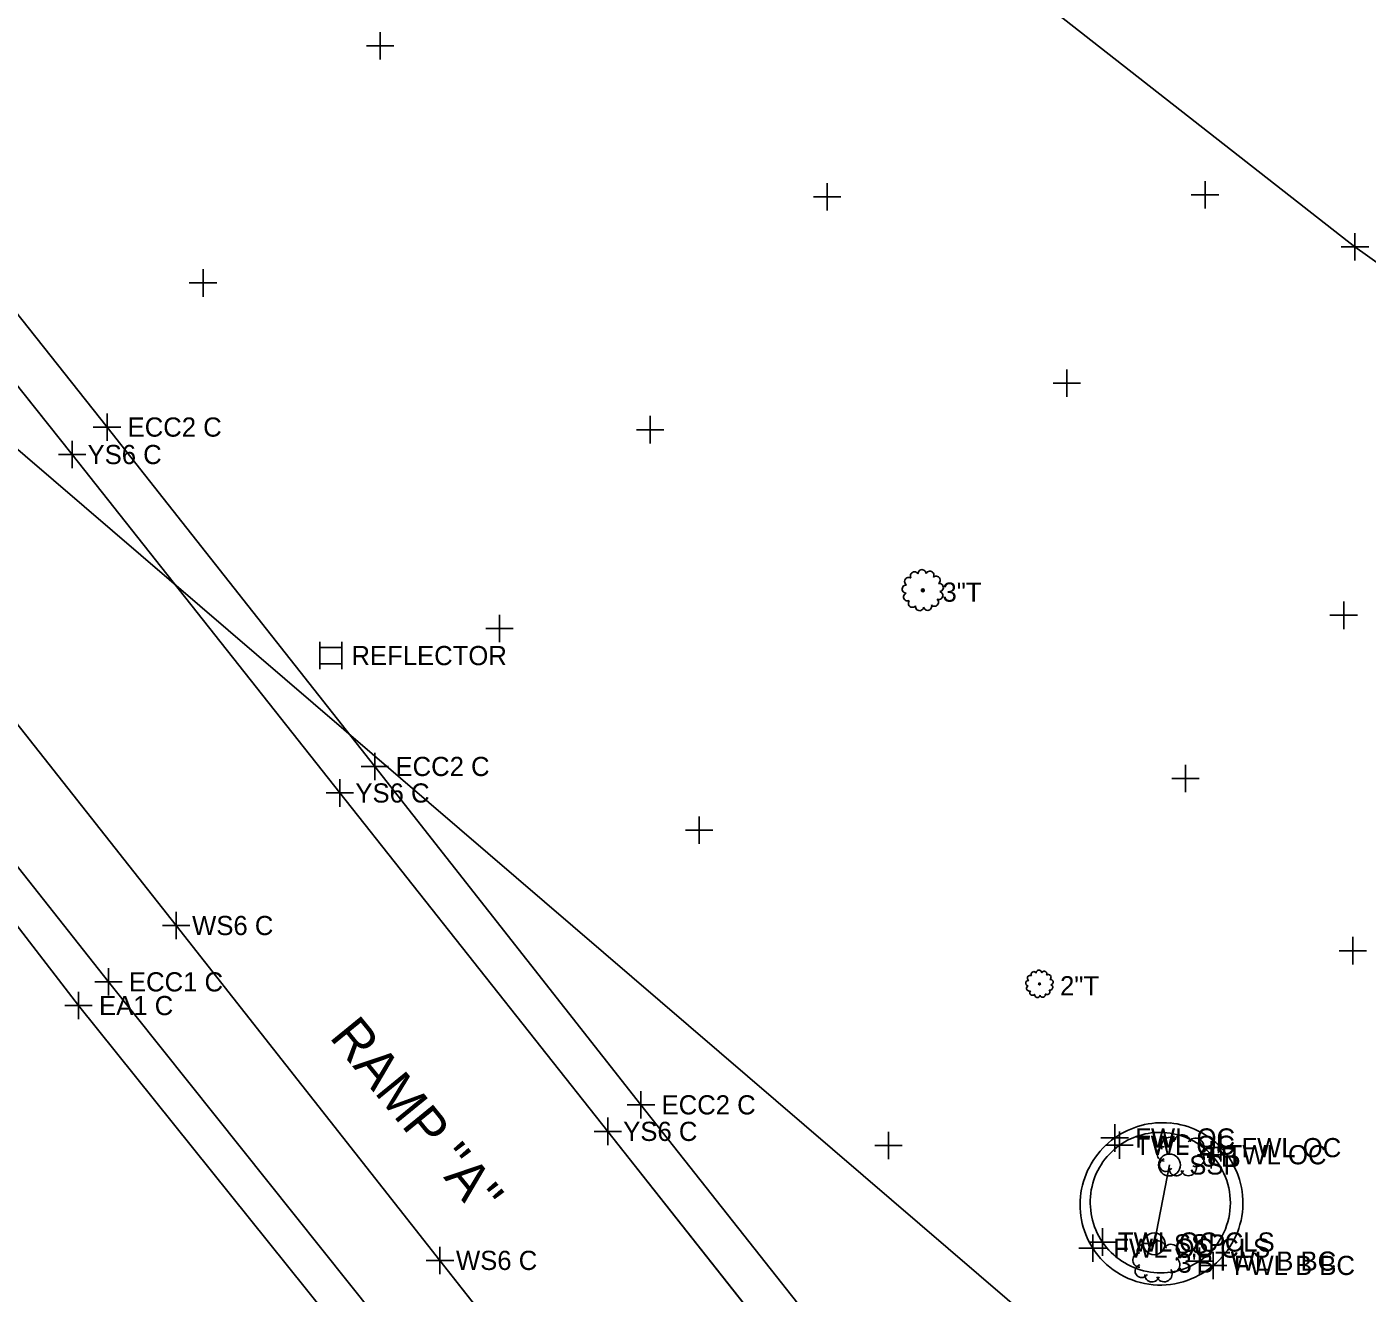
# Model space of a CAD drawing. Extents: x 1324236 to 1326110, y 459090 to 460782.
# Drawn here: x 1324868.3 to 1324966.1, y 460001.4 to 460093.8 of the extents above; entities that cross this region are included whole.
import ezdxf

# ---------------------------------------------------------------- set-up
doc = ezdxf.new("R2010")
doc.units = 0
for name, color, linetype in [('DR_X_Ditch', 7, 'Continuous'), ('DR_X_Drive_Pipe', 7, 'Continuous'), ('DT_X_Contour_Minor', 7, 'Continuous'), ('DT_X_Contour_Text', 7, 'Continuous'), ('DT_X_Terrain_Ground_Line', 7, 'Continuous'), ('DV_X_Property_Line', 7, 'Continuous'), ('E-RW-ODOT', 7, 'Continuous'), ('PM_X_Edge_Line', 7, 'Continuous'), ('PV_X_Shoulder', 7, 'Continuous'), ('RD_X_Text', 7, 'Continuous'), ('RW_X_CL', 7, 'Continuous'), ('RW_X_Esmt_SH', 7, 'Continuous'), ('VG_X_Cells', 7, 'Continuous')]:
    doc.layers.add(name, color=color, linetype=linetype)

msp = doc.modelspace()

# ---------------------------------------------------------------- linework, layer by layer
at = {"layer": 'DR_X_Ditch'}
for points in [[(1324931.111, 459987.395), (1324910.705, 460013.214), (1324891.166, 460037.899), (1324871.627, 460062.59), (1324850.878, 460088.64)], [(1324972.418, 459899.148), (1324970.516, 459905.873), (1324967.972, 459912.382), (1324967.972, 459912.382), (1324965.028, 459918.226), (1324961.566, 459923.779), (1324957.615, 459928.995), (1324957.615, 459928.995), (1324938.831, 459952.603), (1324918.889, 459977.836), (1324898.462, 460003.802), (1324879.212, 460028.231), (1324859.572, 460053.099)]]:
    msp.add_lwpolyline(points, dxfattribs=at)
at = {"layer": 'DR_X_Drive_Pipe'}
for p, q in [((1324939.235, 460098.091), (1324965.213, 460077.743)), ((1324965.213, 460077.743), (1324995.01, 460056.453))]:
    msp.add_line(p, q, dxfattribs=at)
at = {"layer": 'DT_X_Contour_Minor'}
msp.add_line((1324950.563, 460005.008), (1324951.678, 460010.762), dxfattribs=at)
for centre in [(1324951.678, 460010.762), (1324950.563, 460005.008)]:
    msp.add_circle(centre, 0.8, dxfattribs=at)
at = {"layer": 'DT_X_Contour_Text'}
for centre, radius, start, end in [((1324951.177, 460007.826), 6.022, 84.80157, 125.45455), ((1324950.975, 460008.06), 5.075, 84.09181, 125.30471), ((1324950.965, 460007.964), 5.17, 43.27985, 84.09181), ((1324951.193, 460008.002), 5.846, 43.51192, 84.80157), ((1324951.183, 460007.819), 6.032, 125.45455, 168.70241), ((1324950.975, 460008.06), 5.074, 125.30471, 169.93461), ((1324950.998, 460007.995), 5.125, 353.72059, 43.27985), ((1324951.189, 460007.998), 5.852, 356.25143, 43.51192), ((1324951.005, 460007.854), 5.85, 168.70241, 212.65042), ((1324951.07, 460008.043), 5.171, 169.93461, 214.12344), ((1324950.983, 460007.997), 5.14, 304.23642, 353.72059), ((1324951.152, 460008.001), 5.889, 309.14866, 356.25143), ((1324951.011, 460007.858), 5.858, 212.65042, 261.81789), ((1324951.031, 460008.017), 5.125, 214.12344, 258.87056), ((1324951.034, 460008.033), 5.141, 258.87056, 303.54359), ((1324951.016, 460007.896), 5.896, 261.81789, 310.81428)]:
    msp.add_arc(centre, radius, start, end, dxfattribs=at)
at = {"layer": 'DT_X_Terrain_Ground_Line'}
for p, q in [((1324889.704, 460048.924), (1324889.704, 460046.924)), ((1324889.704, 460048.524), (1324891.304, 460048.524)), ((1324891.304, 460048.924), (1324891.304, 460046.924)), ((1324889.704, 460047.323), (1324891.304, 460047.323))]:
    msp.add_line(p, q, dxfattribs=at)
at = {"layer": 'DV_X_Property_Line'}
for p, q in [((1324874.175, 460063.594), (1324874.175, 460065.594)), ((1324873.175, 460064.594), (1324875.175, 460064.594)), ((1324893.717, 460038.834), (1324893.717, 460040.834)), ((1324892.717, 460039.834), (1324894.717, 460039.834)), ((1324874.274, 460023.121), (1324874.274, 460025.121)), ((1324873.274, 460024.121), (1324875.274, 460024.121)), ((1324872.092, 460021.391), (1324872.092, 460023.391)), ((1324871.092, 460022.391), (1324873.092, 460022.391)), ((1324913.127, 460014.149), (1324913.127, 460016.149)), ((1324912.127, 460015.149), (1324914.127, 460015.149)), ((1324947.684, 460011.732), (1324947.684, 460013.732)), ((1324948.042, 460011.201), (1324948.042, 460013.201)), ((1324946.684, 460012.732), (1324948.684, 460012.732)), ((1324947.042, 460012.201), (1324949.042, 460012.201)), ((1324954.729, 460010.509), (1324954.729, 460012.509)), ((1324955.433, 460011.027), (1324955.433, 460013.027)), ((1324953.729, 460011.509), (1324955.729, 460011.509)), ((1324954.433, 460012.027), (1324956.433, 460012.027)), ((1324946.079, 460003.698), (1324946.079, 460005.698)), ((1324946.789, 460004.142), (1324946.789, 460006.142)), ((1324945.079, 460004.698), (1324947.079, 460004.698)), ((1324945.789, 460005.142), (1324947.789, 460005.142)), ((1324953.875, 460002.748), (1324953.875, 460004.748)), ((1324954.87, 460002.434), (1324954.87, 460004.434)), ((1324952.875, 460003.748), (1324954.875, 460003.748)), ((1324953.87, 460003.434), (1324955.87, 460003.434))]:
    msp.add_line(p, q, dxfattribs=at)
at = {"layer": 'E-RW-ODOT'}
msp.add_line((1324967.69, 459977.085), (1324507.192, 460372.321), dxfattribs=at)
at = {"layer": 'PM_X_Edge_Line'}
for p, q in [((1324871.627, 460062.59), (1324850.878, 460088.64)), ((1324891.166, 460037.899), (1324871.627, 460062.59)), ((1324879.212, 460028.231), (1324859.572, 460053.099)), ((1324910.705, 460013.214), (1324891.166, 460037.899)), ((1324898.462, 460003.802), (1324879.212, 460028.231)), ((1324931.111, 459987.395), (1324910.705, 460013.214)), ((1324918.889, 459977.836), (1324898.462, 460003.802))]:
    msp.add_line(p, q, dxfattribs=at)
at = {"layer": 'PV_X_Shoulder'}
for points in [[(1325002.148, 459921.478), (1324996.212, 459922.965), (1324990.513, 459925.196), (1324985.145, 459928.133), (1324985.145, 459928.133), (1324980.413, 459931.549), (1324976.131, 459935.514), (1324972.361, 459939.969), (1324972.361, 459939.969), (1324953.276, 459964.235), (1324933.65, 459989.173), (1324913.127, 460015.149), (1324893.717, 460039.834), (1324874.175, 460064.594), (1324853.444, 460090.73)], [(1324963.956, 459891.113), (1324963.664, 459897.313), (1324962.677, 459903.442), (1324961.01, 459909.421), (1324961.01, 459909.421), (1324958.808, 459914.907), (1324956.032, 459920.127), (1324952.714, 459925.02), (1324952.714, 459925.02), (1324933.824, 459948.865), (1324913.964, 459974.1), (1324893.683, 459999.816), (1324874.274, 460024.121), (1324854.57, 460049.078)], [(1324963.229, 459890.886), (1324962.765, 459896.504), (1324961.703, 459902.039), (1324960.055, 459907.43), (1324960.055, 459907.43), (1324957.85, 459912.595), (1324955.106, 459917.495), (1324951.857, 459922.075), (1324951.857, 459922.075), (1324931.855, 459947.295), (1324912.156, 459972.555), (1324891.509, 459998.228), (1324872.092, 460022.391), (1324852.737, 460047.518)]]:
    msp.add_lwpolyline(points, dxfattribs=at)
at = {"layer": 'RW_X_CL'}
for p, q in [((1324894.1, 460091.41), (1324894.1, 460093.41)), ((1324893.1, 460092.41), (1324895.1, 460092.41)), ((1324954.274, 460080.53), (1324954.274, 460082.53)), ((1324926.704, 460080.396), (1324926.704, 460082.396)), ((1324953.274, 460081.53), (1324955.274, 460081.53)), ((1324925.704, 460081.396), (1324927.704, 460081.396)), ((1324881.176, 460074.103), (1324881.176, 460076.103)), ((1324880.176, 460075.103), (1324882.176, 460075.103)), ((1324944.192, 460066.801), (1324944.192, 460068.801)), ((1324943.192, 460067.801), (1324945.192, 460067.801)), ((1324913.796, 460063.402), (1324913.796, 460065.402)), ((1324912.796, 460064.402), (1324914.796, 460064.402)), ((1324871.627, 460061.59), (1324871.627, 460063.59)), ((1324870.627, 460062.59), (1324872.627, 460062.59)), ((1324964.388, 460049.859), (1324964.388, 460051.859)), ((1324902.802, 460048.89), (1324902.802, 460050.89)), ((1324963.388, 460050.859), (1324965.388, 460050.859)), ((1324901.802, 460049.89), (1324903.802, 460049.89)), ((1324952.846, 460037.954), (1324952.846, 460039.954)), ((1324891.166, 460036.899), (1324891.166, 460038.899)), ((1324951.846, 460038.954), (1324953.846, 460038.954)), ((1324890.166, 460037.899), (1324892.166, 460037.899)), ((1324917.375, 460034.178), (1324917.375, 460036.178)), ((1324916.375, 460035.178), (1324918.375, 460035.178)), ((1324879.212, 460027.231), (1324879.212, 460029.231)), ((1324878.212, 460028.231), (1324880.212, 460028.231)), ((1324965.063, 460025.395), (1324965.063, 460027.395)), ((1324964.063, 460026.395), (1324966.063, 460026.395)), ((1324910.705, 460012.214), (1324910.705, 460014.214)), ((1324909.705, 460013.214), (1324911.705, 460013.214)), ((1324931.176, 460011.176), (1324931.176, 460013.176)), ((1324930.176, 460012.176), (1324932.176, 460012.176)), ((1324898.462, 460002.802), (1324898.462, 460004.802)), ((1324897.462, 460003.802), (1324899.462, 460003.802))]:
    msp.add_line(p, q, dxfattribs=at)
at = {"layer": 'RW_X_Esmt_SH'}
for p, q in [((1324965.213, 460076.743), (1324965.213, 460078.743)), ((1324964.213, 460077.743), (1324966.213, 460077.743))]:
    msp.add_line(p, q, dxfattribs=at)
at = {"layer": 'VG_X_Cells'}
for points in [[(1324933.6, 460052.737), (1324933.689, 460052.685), (1324933.689, 460052.685), (1324933.586, 460052.685)], [(1324933.586, 460052.685), (1324933.689, 460052.685), (1324933.689, 460052.685), (1324933.6, 460052.633)], [(1324933.637, 460052.774), (1324933.689, 460052.685), (1324933.689, 460052.685), (1324933.6, 460052.737)], [(1324933.6, 460052.633), (1324933.689, 460052.685), (1324933.689, 460052.685), (1324933.637, 460052.596)], [(1324933.689, 460052.788), (1324933.689, 460052.685), (1324933.689, 460052.685), (1324933.637, 460052.774)], [(1324933.637, 460052.596), (1324933.689, 460052.685), (1324933.689, 460052.685), (1324933.689, 460052.582)], [(1324933.741, 460052.774), (1324933.689, 460052.685), (1324933.689, 460052.685), (1324933.689, 460052.788)], [(1324933.778, 460052.737), (1324933.689, 460052.685), (1324933.689, 460052.685), (1324933.741, 460052.774)], [(1324933.792, 460052.685), (1324933.689, 460052.685), (1324933.689, 460052.685), (1324933.778, 460052.737)], [(1324933.689, 460052.582), (1324933.689, 460052.685), (1324933.689, 460052.685), (1324933.741, 460052.596)], [(1324933.741, 460052.596), (1324933.689, 460052.685), (1324933.689, 460052.685), (1324933.778, 460052.633)], [(1324933.778, 460052.633), (1324933.689, 460052.685), (1324933.689, 460052.685), (1324933.792, 460052.685)], [(1324942.138, 460024.002), (1324942.197, 460023.968), (1324942.197, 460023.968), (1324942.128, 460023.968)], [(1324942.128, 460023.968), (1324942.197, 460023.968), (1324942.197, 460023.968), (1324942.138, 460023.934)], [(1324942.163, 460024.027), (1324942.197, 460023.968), (1324942.197, 460023.968), (1324942.138, 460024.002)], [(1324942.138, 460023.934), (1324942.197, 460023.968), (1324942.197, 460023.968), (1324942.163, 460023.909)], [(1324942.197, 460024.037), (1324942.197, 460023.968), (1324942.197, 460023.968), (1324942.163, 460024.027)], [(1324942.163, 460023.909), (1324942.197, 460023.968), (1324942.197, 460023.968), (1324942.197, 460023.899)], [(1324942.231, 460024.027), (1324942.197, 460023.968), (1324942.197, 460023.968), (1324942.197, 460024.037)], [(1324942.256, 460024.002), (1324942.197, 460023.968), (1324942.197, 460023.968), (1324942.231, 460024.027)], [(1324942.266, 460023.968), (1324942.197, 460023.968), (1324942.197, 460023.968), (1324942.256, 460024.002)], [(1324942.197, 460023.899), (1324942.197, 460023.968), (1324942.197, 460023.968), (1324942.231, 460023.909)], [(1324942.231, 460023.909), (1324942.197, 460023.968), (1324942.197, 460023.968), (1324942.256, 460023.934)], [(1324942.256, 460023.934), (1324942.197, 460023.968), (1324942.197, 460023.968), (1324942.266, 460023.968)]]:
    msp.add_lwpolyline(points, close=True, dxfattribs=at)
for points in [[(1324951.302, 460012.09), (1324951.205, 460012.081), (1324951.113, 460012.055), (1324951.026, 460012.012), (1324950.95, 460011.954), (1324950.885, 460011.882), (1324950.834, 460011.8), (1324950.799, 460011.71), (1324950.781, 460011.616), (1324950.781, 460011.519), (1324950.799, 460011.425), (1324950.834, 460011.335), (1324950.885, 460011.253), (1324950.95, 460011.181), (1324951.026, 460011.123), (1324951.113, 460011.08), (1324951.205, 460011.054), (1324951.302, 460011.045)], [(1324952.172, 460012.612), (1324952.074, 460012.686), (1324951.964, 460012.74), (1324951.846, 460012.772), (1324951.724, 460012.781), (1324951.602, 460012.767), (1324951.486, 460012.73), (1324951.378, 460012.672), (1324951.283, 460012.595), (1324951.204, 460012.501), (1324951.144, 460012.394), (1324951.106, 460012.278), (1324951.09, 460012.157), (1324951.097, 460012.034), (1324951.127, 460011.916)], [(1324953.217, 460012.438), (1324953.19, 460012.552), (1324953.141, 460012.659), (1324953.073, 460012.754), (1324952.989, 460012.835), (1324952.89, 460012.898), (1324952.781, 460012.942), (1324952.666, 460012.964), (1324952.549, 460012.964), (1324952.434, 460012.942), (1324952.325, 460012.898), (1324952.227, 460012.835), (1324952.142, 460012.754), (1324952.074, 460012.659), (1324952.026, 460012.552), (1324951.998, 460012.438)], [(1324953.914, 460011.568), (1324954.005, 460011.641), (1324954.08, 460011.73), (1324954.138, 460011.831), (1324954.176, 460011.942), (1324954.193, 460012.057), (1324954.188, 460012.174), (1324954.162, 460012.288), (1324954.115, 460012.394), (1324954.049, 460012.491), (1324953.966, 460012.573), (1324953.87, 460012.639), (1324953.763, 460012.686), (1324953.649, 460012.712), (1324953.533, 460012.717), (1324953.417, 460012.7), (1324953.307, 460012.662), (1324953.206, 460012.604), (1324953.117, 460012.529), (1324953.043, 460012.438)], [(1324951.302, 460011.219), (1324951.215, 460011.187), (1324951.136, 460011.14), (1324951.068, 460011.077), (1324951.014, 460011.003), (1324950.975, 460010.919), (1324950.953, 460010.83), (1324950.949, 460010.737), (1324950.963, 460010.646), (1324950.995, 460010.56), (1324951.043, 460010.481), (1324951.105, 460010.413), (1324951.179, 460010.358), (1324951.263, 460010.319), (1324951.352, 460010.297), (1324951.444, 460010.293), (1324951.536, 460010.307), (1324951.622, 460010.338), (1324951.701, 460010.386), (1324951.769, 460010.448), (1324951.824, 460010.523)], [(1324953.391, 460010.697), (1324953.497, 460010.662), (1324953.607, 460010.647), (1324953.718, 460010.654), (1324953.826, 460010.681), (1324953.926, 460010.729), (1324954.016, 460010.794), (1324954.092, 460010.876), (1324954.151, 460010.97), (1324954.191, 460011.074), (1324954.211, 460011.183), (1324954.209, 460011.294), (1324954.187, 460011.403), (1324954.144, 460011.506), (1324954.083, 460011.599), (1324954.005, 460011.678), (1324953.914, 460011.742)], [(1324951.65, 460010.523), (1324951.656, 460010.42), (1324951.681, 460010.32), (1324951.725, 460010.227), (1324951.786, 460010.145), (1324951.861, 460010.075), (1324951.949, 460010.021), (1324952.045, 460009.985), (1324952.147, 460009.968), (1324952.249, 460009.971), (1324952.35, 460009.994), (1324952.444, 460010.035), (1324952.528, 460010.093), (1324952.6, 460010.167), (1324952.656, 460010.253), (1324952.695, 460010.348)], [(1324952.521, 460010.348), (1324952.573, 460010.247), (1324952.644, 460010.158), (1324952.731, 460010.084), (1324952.83, 460010.029), (1324952.938, 460009.994), (1324953.052, 460009.98), (1324953.165, 460009.989), (1324953.275, 460010.019), (1324953.377, 460010.07), (1324953.467, 460010.139), (1324953.542, 460010.225), (1324953.599, 460010.324), (1324953.635, 460010.432), (1324953.651, 460010.544), (1324953.644, 460010.658), (1324953.615, 460010.768), (1324953.566, 460010.871)], [(1324949.527, 460004.347), (1324949.43, 460004.338), (1324949.338, 460004.312), (1324949.251, 460004.269), (1324949.175, 460004.211), (1324949.11, 460004.139), (1324949.059, 460004.057), (1324949.024, 460003.967), (1324949.006, 460003.873), (1324949.006, 460003.776), (1324949.024, 460003.682), (1324949.059, 460003.592), (1324949.11, 460003.51), (1324949.175, 460003.438), (1324949.251, 460003.38), (1324949.338, 460003.337), (1324949.43, 460003.311), (1324949.527, 460003.302)], [(1324950.397, 460004.869), (1324950.299, 460004.943), (1324950.189, 460004.997), (1324950.071, 460005.029), (1324949.949, 460005.038), (1324949.827, 460005.024), (1324949.711, 460004.987), (1324949.603, 460004.929), (1324949.508, 460004.852), (1324949.429, 460004.758), (1324949.369, 460004.651), (1324949.331, 460004.535), (1324949.315, 460004.414), (1324949.322, 460004.291), (1324949.352, 460004.173)], [(1324951.442, 460004.695), (1324951.415, 460004.809), (1324951.366, 460004.916), (1324951.298, 460005.011), (1324951.214, 460005.092), (1324951.115, 460005.155), (1324951.006, 460005.199), (1324950.891, 460005.221), (1324950.774, 460005.221), (1324950.659, 460005.199), (1324950.55, 460005.155), (1324950.452, 460005.092), (1324950.367, 460005.011), (1324950.299, 460004.916), (1324950.251, 460004.809), (1324950.223, 460004.695)], [(1324952.139, 460003.825), (1324952.23, 460003.898), (1324952.305, 460003.987), (1324952.363, 460004.088), (1324952.401, 460004.199), (1324952.418, 460004.314), (1324952.413, 460004.431), (1324952.387, 460004.545), (1324952.34, 460004.651), (1324952.274, 460004.748), (1324952.191, 460004.83), (1324952.095, 460004.896), (1324951.988, 460004.943), (1324951.874, 460004.969), (1324951.758, 460004.974), (1324951.642, 460004.957), (1324951.532, 460004.919), (1324951.431, 460004.861), (1324951.342, 460004.786), (1324951.268, 460004.695)], [(1324949.527, 460003.476), (1324949.44, 460003.444), (1324949.361, 460003.397), (1324949.293, 460003.334), (1324949.239, 460003.26), (1324949.2, 460003.176), (1324949.178, 460003.087), (1324949.174, 460002.994), (1324949.188, 460002.903), (1324949.22, 460002.817), (1324949.268, 460002.738), (1324949.33, 460002.67), (1324949.404, 460002.615), (1324949.488, 460002.576), (1324949.577, 460002.554), (1324949.669, 460002.55), (1324949.761, 460002.564), (1324949.847, 460002.595), (1324949.926, 460002.643), (1324949.994, 460002.705), (1324950.049, 460002.78)], [(1324951.616, 460002.954), (1324951.722, 460002.919), (1324951.832, 460002.904), (1324951.943, 460002.911), (1324952.051, 460002.938), (1324952.151, 460002.986), (1324952.241, 460003.051), (1324952.317, 460003.133), (1324952.376, 460003.227), (1324952.416, 460003.331), (1324952.436, 460003.44), (1324952.434, 460003.551), (1324952.412, 460003.66), (1324952.369, 460003.763), (1324952.308, 460003.856), (1324952.23, 460003.935), (1324952.139, 460003.999)], [(1324949.875, 460002.78), (1324949.881, 460002.677), (1324949.906, 460002.577), (1324949.95, 460002.484), (1324950.011, 460002.402), (1324950.086, 460002.332), (1324950.174, 460002.278), (1324950.27, 460002.242), (1324950.372, 460002.225), (1324950.474, 460002.228), (1324950.575, 460002.251), (1324950.669, 460002.292), (1324950.753, 460002.35), (1324950.825, 460002.424), (1324950.881, 460002.51), (1324950.92, 460002.605)], [(1324950.746, 460002.605), (1324950.798, 460002.504), (1324950.869, 460002.415), (1324950.956, 460002.341), (1324951.055, 460002.286), (1324951.163, 460002.251), (1324951.277, 460002.237), (1324951.39, 460002.246), (1324951.5, 460002.276), (1324951.602, 460002.327), (1324951.692, 460002.396), (1324951.767, 460002.482), (1324951.824, 460002.581), (1324951.86, 460002.689), (1324951.876, 460002.801), (1324951.869, 460002.915), (1324951.84, 460003.025), (1324951.791, 460003.128)]]:
    msp.add_lwpolyline(points, dxfattribs=at)
for centre, radius, start, end in [((1324933.632, 460053.898), 0.298, 1.24102, 184.12371), ((1324932.658, 460053.327), 0.298, 56.62564, 239.50832), ((1324933.075, 460053.733), 0.298, 28.93333, 211.81601), ((1324934.202, 460053.786), 0.298, 333.54871, 156.4314), ((1324934.655, 460053.421), 0.298, 305.85641, 128.73909), ((1324934.887, 460052.888), 0.298, 278.1641, 101.04678), ((1324932.478, 460052.775), 0.298, 84.31794, 267.20063), ((1324932.575, 460052.202), 0.298, 112.01025, 294.89294), ((1324934.844, 460052.308), 0.298, 250.47179, 73.35448), ((1324932.927, 460051.739), 0.298, 139.70256, 322.58525), ((1324933.454, 460051.493), 0.298, 167.39487, 350.27755), ((1324934.035, 460051.521), 0.298, 195.08718, 17.96986), ((1324934.536, 460051.815), 0.298, 222.77948, 45.66217), ((1324941.788, 460024.667), 0.198, 28.93333, 211.81601), ((1324942.159, 460024.777), 0.198, 1.24102, 184.12371), ((1324942.539, 460024.702), 0.198, 333.54871, 156.4314), ((1324941.39, 460024.028), 0.198, 84.31794, 267.20063), ((1324941.454, 460023.646), 0.198, 112.01025, 294.89294), ((1324941.51, 460024.396), 0.198, 56.62564, 239.50832), ((1324942.841, 460024.459), 0.198, 305.85641, 128.73909), ((1324942.967, 460023.717), 0.198, 250.47179, 73.35448), ((1324942.995, 460024.103), 0.198, 278.1641, 101.04678), ((1324941.689, 460023.337), 0.198, 139.70256, 322.58525), ((1324942.04, 460023.174), 0.198, 167.39487, 350.27755), ((1324942.427, 460023.192), 0.198, 195.08718, 17.96986), ((1324942.762, 460023.388), 0.198, 222.77948, 45.66217)]:
    msp.add_arc(centre, radius, start, end, dxfattribs=at)

# ---------------------------------------------------------------- texts
at = {"layer": 'DT_X_Contour_Minor'}
for p in [(1324953.124, 460010.062), (1324952.009, 460004.308)]:
    msp.add_text('SSP', height=1.4, dxfattribs=at).set_placement(p)
at = {"layer": 'DV_X_Property_Line'}
for s, p in [('ECC2 C', (1324875.675, 460063.894)), ('ECC2 C', (1324895.217, 460039.134)), ('ECC1 C', (1324875.774, 460023.421)), ('EA1 C', (1324873.592, 460021.691)), ('ECC2 C', (1324914.627, 460014.449)), ('FWL OC', (1324949.184, 460012.032)), ('TWL OC', (1324949.167, 460011.501)), ('TWL OC', (1324955.854, 460010.809)), ('FWL OC', (1324956.933, 460011.327)), ('FWL OC CLS', (1324947.579, 460003.998)), ('TWL OC CLS', (1324947.914, 460004.442)), ('TWL B BC', (1324955, 460003.048)), ('FWL B BC', (1324956.37, 460002.734))]:
    msp.add_text(s, height=1.4, dxfattribs=at).set_placement(p)
at = {"layer": 'RD_X_Text'}
msp.add_text('RAMP "A"', height=2.8, rotation=309.22083, dxfattribs=at).set_placement((1324890.335, 460020.074))
at = {"layer": 'RW_X_CL'}
for s, p in [('YS6 C', (1324872.752, 460061.89)), ('YS6 C', (1324892.291, 460037.199)), ('WS6 C', (1324880.379, 460027.531)), ('YS6 C', (1324911.83, 460012.514)), ('WS6 C', (1324899.629, 460003.102))]:
    msp.add_text(s, height=1.4, dxfattribs=at).set_placement(p)
at = {"layer": 'RW_X_Esmt_SH'}
msp.add_text('REFLECTOR', height=1.4, dxfattribs=at).set_placement((1324892.004, 460047.224))
at = {"layer": 'VG_X_Cells'}
for s, p in [('3"T', (1324935.118, 460051.852)), ('2"T', (1324943.697, 460023.135)), ("3'B", (1324954.036, 460010.643)), ("3'B", (1324952.261, 460002.9))]:
    msp.add_text(s, height=1.4, dxfattribs=at).set_placement(p)

doc.saveas('drawing.dxf')
